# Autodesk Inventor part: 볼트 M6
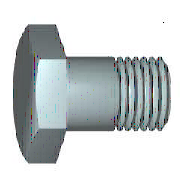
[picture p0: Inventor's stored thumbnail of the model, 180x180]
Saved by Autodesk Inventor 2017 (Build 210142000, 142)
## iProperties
IsCustomPart: 0
Created: 2012-02
Part Number: 볼트 M6
Material: 스테인리스강
Description: 6각 머리 나사. 제품 등급 C
Document SubType Name: Modeling
Standard: ISO 4018
Designer: mduedu
Standard Revision: Third edition 1999-08-15
Standards Organization: ISO
Language: ko-KR
Size Designation: M6 x 12
Categories: <MemberInstance><Categories><Category DisplayName="조임쇠" InternalName="e4da775c-781d-43d5-af7c-5136215cf5a6" Mnemonic="FSTN"><Category DisplayName="볼트" InternalN
Density: 8.08 g/cm^3
Mass: 5.05889 g
Surface Area: 4.88365 cm^2
Volume: 0.6261 cm^3
Appearance: 반광택
Author: mduedu
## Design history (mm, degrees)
node "WorkPlane1"
node "WorkPoint1"
node "MSC_A1"
node "MSC_PF1"
node "MSC_PT1"
body "Solid1"
node "스케치1"
sketch "스케치2"
  geometry: L1 (-5, 2.887)-(-5, -2.887); L2 (0, 5.773)-(-5, 2.887); L3 (5, 2.887)-(0, 5.773); L4 (5, -2.887)-(5, 2.887); L5 (0, -5.773)-(5, -2.887); L6 (-5, -2.887)-(0, -5.773); C1 r 5 at (0, 0); 1 further point
  constraints: 12 end point, 6 tangent, 2 parallel, 2 vertical, 1 centre point
  dimensions: "d1" = 10 diameter of C1 (= ParS); "d29" = 0 distance of point (0, 0) C1.centre; "d30" = 0 distance of C1.centre point (0, 0)
extrude "돌출1" new body sketch "스케치2" distance "d6" = 4 (= ParK); taper "d7" = 0 deg
revolve "회전1" stored, may be unused: angle "d14" = 360 deg
revolve "회전2" stored, may be unused: angle "d21" = 360 deg
chamfer "모따기1" distance "d22" = 0.5 (= 0.5 x PTC); stored, may be unused: second distance "d23" = 0.5 (= 0.5 x PTC), angle "d39" = 45 deg
fillet "모깎기1" dims "d24" = 0.25 (= r)
feature "스레드1" dims "d32" = 0, "b" = 8.5 (= NLG - 1.5 x PTC)
sketch "스케치3"
  geometry: L1 (5, 4)-(5.873, 4); L2 (5.873, 3.496)-(5, 4); L3 (5.873, 4)-(5.873, 3.496); L4 (0, -0.8)-(0, 4.8) reference; L5 (5.773, 0)-(5.773, 4) reference
  constraints: 6 end point, 1 horizontal, 1 vertical
  dimensions: "d25" = 0.1 distance between parallel lines of L5 L3; "d26" = 0 distance from line of L5.end L1; "d27" = 60 deg angle of L3 L2; "d28" = 5 distance from line of L4 L1.start (= 0.5 x ParS)
sketch "스케치4"
  geometry: L1 (0, -10)-(0, 0); L2 (-3, -10)-(0, -10); L3 (-3, 0)-(-3, -10); L4 (0, 0)-(-3, 0); L5 (0, -10)-(0, 0); L6 (-3.6, 0)-(0.6, 0) reference; L7 (0, -14.4)-(0, 2.4) reference
  constraints: 10 end point, 2 horizontal, 2 vertical
  dimensions: "d18" = 3 distance of L1.start L2.start (= 0.5 x NND); "d20" = 10 distance of L3.start L2.start (= NLG); "d33" = 0 distance between parallel lines of L7 L1; "d34" = 0 distance between parallel lines of L6 L4
other parameters: "NND" = 6 [user parameter; used in 2 equation terms], "NLG" = 10 [user parameter; used in 2 equation terms], "PTC" = 1 [user parameter; used in 3 equation terms], "ParK" = 4 [user parameter; used in 1 equation term], "ParS" = 10 [user parameter; used in 3 equation terms], "msp_es" = 5.77367 (= 0.577367 x ParS) [user parameter], "r" = 0.25 [user parameter; used in 1 equation term], "d2" = 15 (derived), "d4" = 17.32102 (derived), "d8" = 15 (derived), "d10" = 0 (derived), "d12" = 30 deg (derived), "d15" = 0 (derived), "d37" = 0, "d38" = 0, "d40" = 0, "d41" = 0, "d42" = 0, "THREADDIA" = 6 (= NND) [user parameter]
